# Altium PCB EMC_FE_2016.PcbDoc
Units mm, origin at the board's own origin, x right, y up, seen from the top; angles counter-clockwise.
Board outline 100 x 50 mm, 2 copper layers (Top Layer, Bottom Layer), stack 1.55 mm thick; 86 components, 30 nets, 176 pads, 0 vias.
Unrouted connection lines stored in the file: 116.
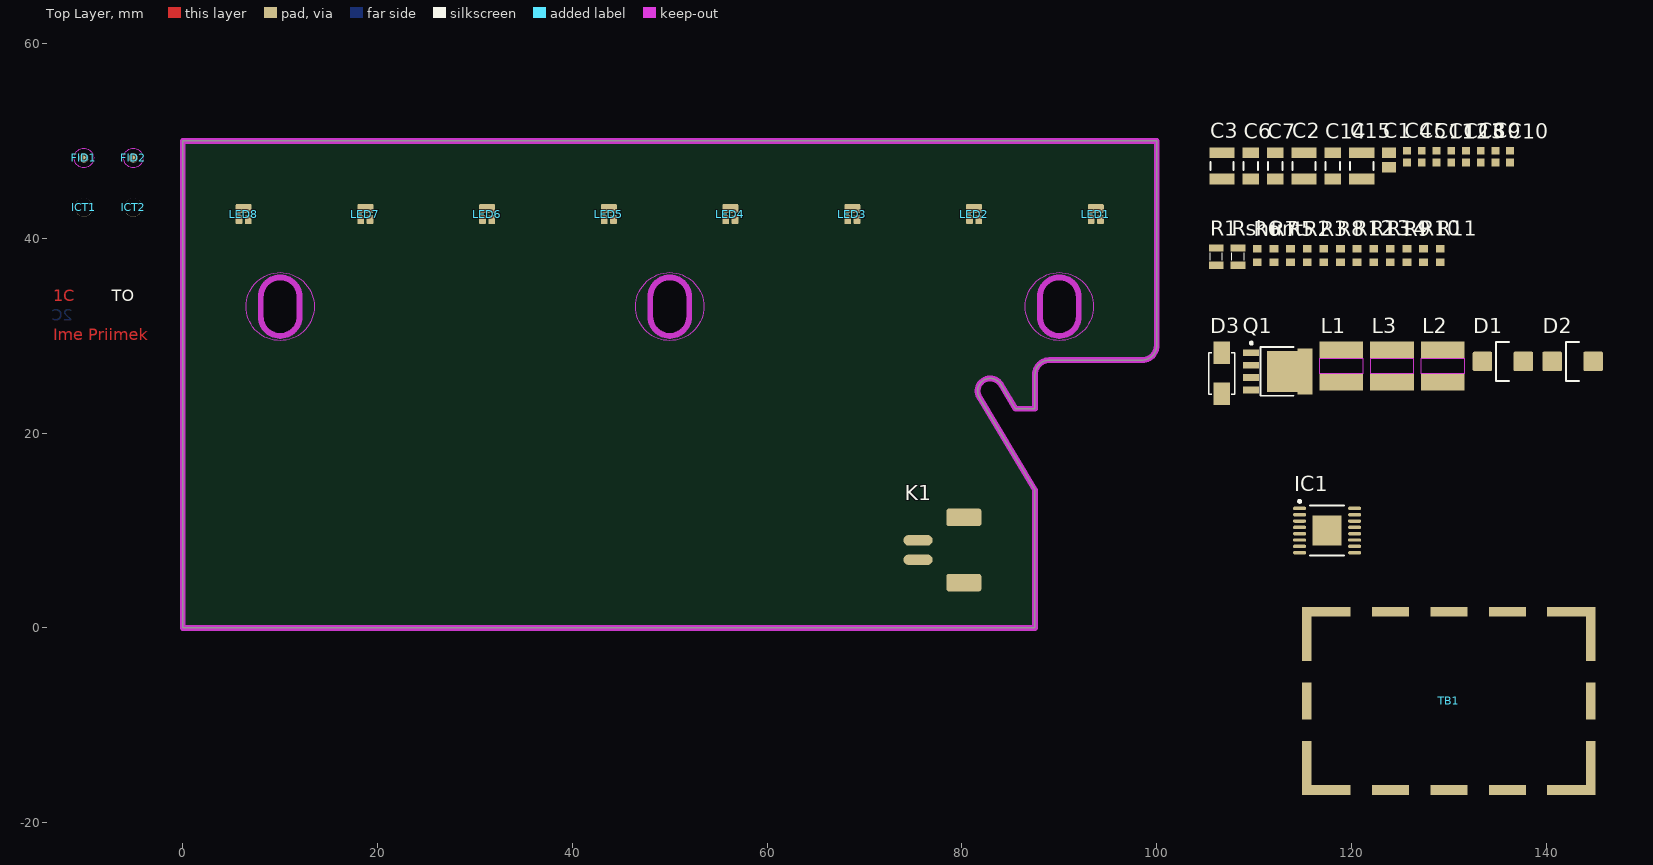
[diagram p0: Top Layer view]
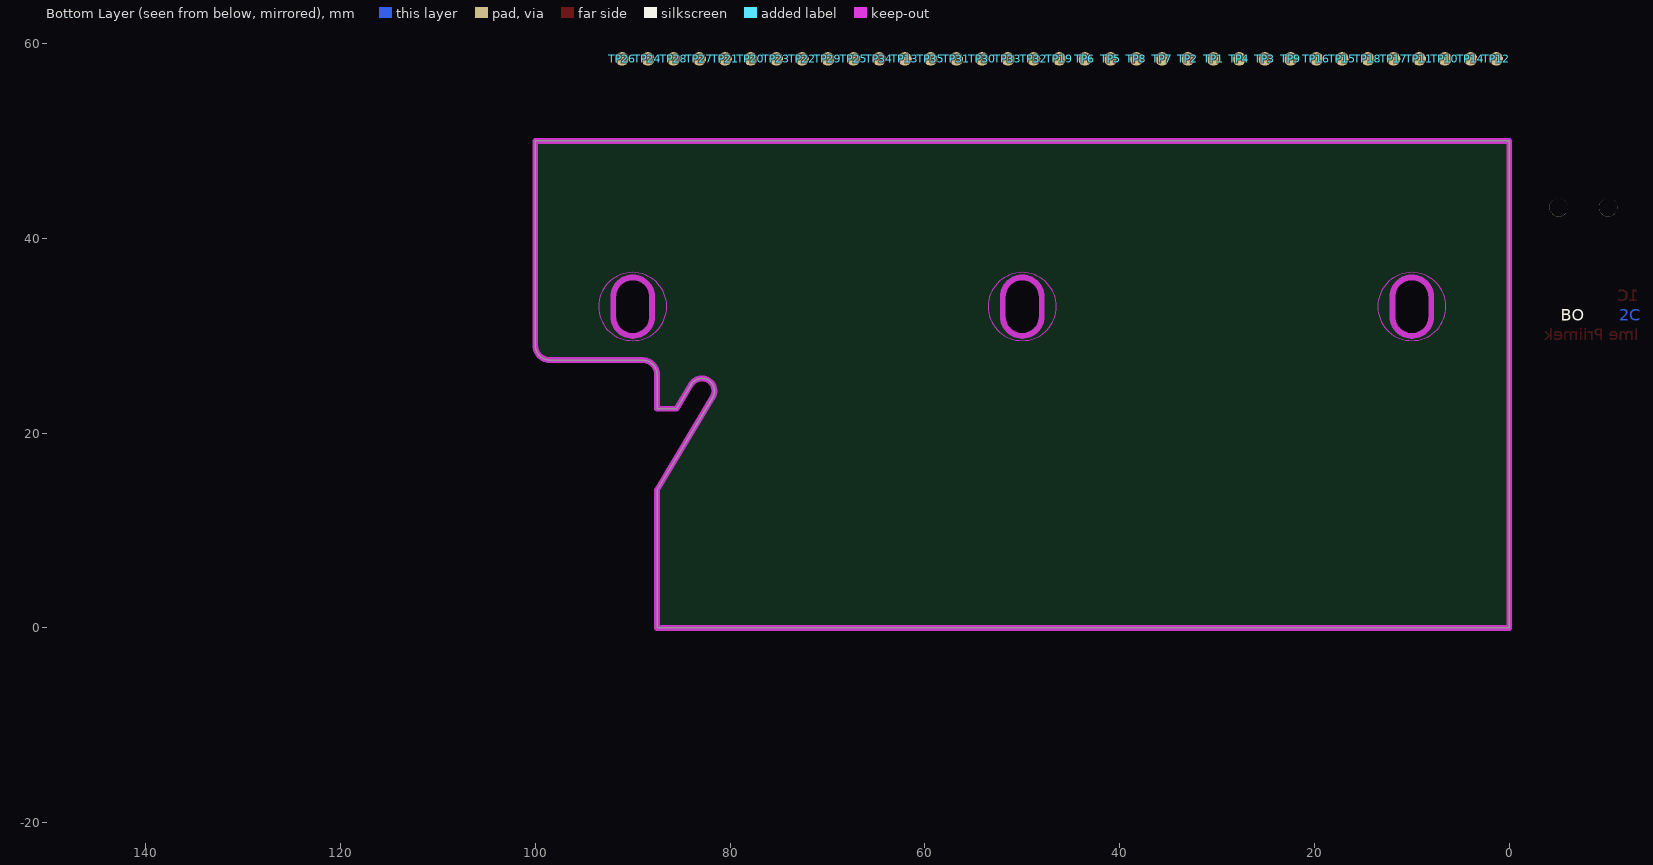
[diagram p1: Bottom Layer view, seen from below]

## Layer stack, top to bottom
Top Solder: solder mask 0.0102, Solder Resist, Dk 3.5
Top Layer: signal copper 0.07
Dielectric1: core 1.41, FR-4, Dk 4.8
Bottom Layer: signal copper 0.07
Bottom Solder: solder mask 0.0102, Solder Resist, Dk 3.5

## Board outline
0,0 0,50 100,50 100,29 cw(c98.5,29) 98.5,27.5 89,27.5 ccw(c89,26) 87.5,26 87.5,22.5 85.5,22.5 84,25 ccw(c82.897,24.338) 81.794,23.676 87.5,14.167 87.5,0
cut-out: 8,31.99 ccw(c10,31.99) 12,31.99 12,33.99 ccw(c10,33.99) 8,33.99
cut-out: 48,31.99 ccw(c50,31.99) 52,31.99 52,33.99 ccw(c50,33.99) 48,33.99
cut-out: 88,31.99 ccw(c90,31.99) 92,31.99 92,33.99 ccw(c90,33.99) 88,33.99

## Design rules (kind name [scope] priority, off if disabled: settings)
AssemblyTestPointUsage SilkToBoardRegionClearance [All] p2:
AssemblyTestPointUsage UnpouredPolygon [All] p3:
AssemblyTestpoint [(IsPad And OnBottomLayer)] p1: testpointundercomponent=TRUE minsize=1.016 maxsize=2.54 preferedsize=1.524 minholesize=0 maxholesize=1.016 preferedholesize=0.813 testpointgrid=0.025 usegrid=FALSE gridtolerance=0 allowsidebottom=TRUE
Clearance Clearance_GND [(InNamedPolygon('Bottom Layer-No Net'))] p1: gap=0.3
Clearance Clearance_LED [HasFootprint('LUXEON_F_CW')] p2: gap=0.25
Clearance [All] p3: gap=0.3
FabricationTestpoint [(IsPad And OnBottomLayer)] p1: side=2 testpointundercomponent=FALSE minsize=1.016 maxsize=2.54 preferedsize=1.524 minholesize=0 maxholesize=1.016 preferedholesize=0.813 testpointgrid=0.025 allowsidebottom=TRUE usegrid=FALSE gridtolerance=0 minspacing=2.54 boardedgeclearance=1
Height [All] p1: minheight=-1 maxheight=50 prefheight=12.7
HoleSize [All] p1: absolutevalues=TRUE maxlimit=6.096 minlimit=0.356 maxpercent=80.000 minpercent=20.000
HoleToHoleClearance [All] p1: gap=0.203 allowstackedmicrovias=TRUE
MinimumSolderMaskSliver [All] p1: minsoldermaskwidth=0.076
PlaneClearance [All] p1: clearance=0.305
PlaneConnect [All] p1: planeconnectstyle=Relief reliefexpansion=0.508 reliefentries=4 reliefconductorwidth=0.3 reliefairgap=0.3
PolygonConnect PolygonConnect_via [IsVia] p1: connectstyle=Direct reliefconductorwidth=0.254 reliefentries=4 polygonreliefangle="90 Angle" airgapwidth=0.254
PolygonConnect PolygonConnect_PadGND [(HasFootprint('BMI-S-209-F') OR HasFootprint('MXA16A_M')) AND InNet('GND')] p2: connectstyle=Direct reliefconductorwidth=0.254 reliefentries=4 polygonreliefangle="90 Angle" airgapwidth=0.254
PolygonConnect [All] p3: connectstyle=Relief reliefconductorwidth=0.305 reliefentries=4 polygonreliefangle="90 Angle" airgapwidth=0.305
RoutingVias [All] p1: holewidth=0.5 width=0.9 viastyle="Through Hole" minholewidth=0.4 minwidth=0.7 maxholewidth=0.7 maxwidth=1.2
ShortCircuit fill [IsFill And IsKeepOut vs IsPad] p1: allowed=TRUE
ShortCircuit ShortCircuit_GND [InNet('AGND') OR InNet('GND') OR InNet('QGND') OR InNet('PGND') OR InNet('REF_GND') vs InNet('AGND') OR InNet('GND') OR InNet('QGND') OR InNet('PGND') OR InNet('REF_GND')] p2: allowed=TRUE
ShortCircuit [All] p3: allowed=FALSE
SilkToBoardRegionClearance SilkToBoardRegionClearance_1 [All] p1:
SilkToSilkClearance [All] p1: silktosilkclearance=0.102
SilkToSolderMaskClearance SilkscreenOverComponentPads [IsPad] p1: minsilkscreentomaskgap=0.05 clearancetoexposedcopper=TRUE
SolderMaskExpansion [All] p1: expansion=0.102
UnpouredPolygon UnpouredPolygon_1 [All] p1:
Width [All] p1: maxlimit=0.5 minlimit=0.2 preferedwidth=0.3
17 further rules are at their usual default settings.

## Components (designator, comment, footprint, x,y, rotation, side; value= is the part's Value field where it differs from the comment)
C1 "?" C0805 123.852,48.042 r90 top
C2 "?" C1210 115.128,47.442 r90 top
C3 "?" C1210 106.704,47.442 r90 top
C4 "?" C0603 125.712,48.39 r90 top
C5 "?" C0603 127.223,48.39 r90 top
C6 "?" C1206 109.662,47.442 r90 top
C7 "?" C1206 112.17,47.442 r90 top
C8 "?" C0603 133.268,48.39 r90 top
C9 "?" C0603 134.779,48.39 r90 top
C10 "?" C0603 136.29,48.39 r90 top
C11 "?" C0603 128.734,48.39 r90 top
C12 "?" C0603 130.245,48.39 r90 top
C13 "?" C0603 131.756,48.39 r90 top
C14 "?" C1206 118.086,47.442 r90 top
C15 "?" C1210 121.044,47.442 r90 top
D1 "SS26" DO-214AA 135.549,27.367 r0 top
D2 "SS26" DO-214AA 142.707,27.367 r0 top
D3 "Bidirectional, 400 W, 36 VDC" DO-214AC_Bidirectional 106.665,26.14 r90 top
FID1 "Fiducial" FIDUCIAL -10.16,48.26 r90 top
FID2 "Fiducial" FIDUCIAL -5.08,48.26 r90 top
IC1 "TPS92690-Q1" MXA16A_L 117.5,10 r0 top
ICT1 "ICT" ICT_19 -10.16,43.18 r90 top
ICT2 "ICT" ICT_19 -5.08,43.18 r90 top
K1 "BM02B-PASS" BM02B-PASS 79,8 r90 top
L1 "?" WE-PD2A_4532 118.941,26.89 r0 top
L2 "?" WE-PD2A_4532 129.364,26.89 r0 top
L3 "?" WE-PD2A_4532 124.152,26.89 r0 top
LED1 "LFXH-C1A-0100" LUXEON_F_CW 93.75,42.525 r0 top locked
LED2 "LFXH-C1A-0100" LUXEON_F_CW 81.25,42.525 r0 top locked
LED3 "LFXH-C1A-0100" LUXEON_F_CW 68.75,42.525 r0 top locked
LED4 "LFXH-C1A-0100" LUXEON_F_CW 56.225,42.525 r0 top locked
LED5 "LFXH-C1A-0100" LUXEON_F_CW 43.75,42.525 r0 top locked
LED6 "LFXH-C1A-0100" LUXEON_F_CW 31.25,42.525 r0 top locked
LED7 "LFXH-C1A-0100" LUXEON_F_CW 18.75,42.525 r0 top locked
LED8 "LFXH-C1A-0100" LUXEON_F_CW 6.25,42.525 r0 top locked
Q1 "BUK9Y59-60E" LFPAK56 112.436,26.342 r0 top
R1 "?" R0805 106.118,38.12 r90 top
R2 "?" R0603 115.448,38.242 r90 top
R3 "100" R0603 117.156,38.242 r90 top
R5 "?" R0603 113.74,38.242 r90 top
R6 "?" R0603 110.324,38.242 r90 top
R7 "?" R0603 112.032,38.242 r90 top
R8 "?" R0603 118.864,38.242 r90 top
R9 "?" R0603 125.696,38.242 r90 top
R10 "?" R0603 127.404,38.242 r90 top
R11 "?" R0603 129.112,38.242 r90 top
R12 "?" R0603 120.572,38.242 r90 top
R13 "?" R0603 122.28,38.242 r90 top
R14 "?" R0603 123.988,38.242 r90 top
Rshunt "?" R0805 108.353,38.12 r90 top
TB1 "BMI-S-209-F" BMI-S-209-F 130,-7.5 r180 top
TP1 "TP?" Test_point_14 30.36,58.426 r180 bottom
TP2 "TP?" Test_point_14 33,58.426 r180 bottom
TP3 "TP?" Test_point_14 25.08,58.426 r180 bottom
TP4 "TP?" Test_point_14 27.72,58.426 r180 bottom
TP5 "TP?" Test_point_14 40.92,58.426 r180 bottom
TP6 "TP?" Test_point_14 43.56,58.426 r180 bottom
TP7 "TP?" Test_point_14 35.64,58.426 r180 bottom
TP8 "TP?" Test_point_14 38.28,58.426 r180 bottom
TP9 "TP?" Test_point_14 22.44,58.426 r180 bottom
TP10 "TP?" Test_point_14 6.6,58.426 r90 bottom
TP11 "TP?" Test_point_14 9.24,58.426 r90 bottom
TP12 "TP?" Test_point_14 1.32,58.426 r90 bottom
TP13 "TP?" Test_point_14 62.04,58.426 r90 bottom
TP14 "TP?" Test_point_14 3.96,58.426 r90 bottom
TP15 "TP?" Test_point_14 17.16,58.426 r90 bottom
TP16 "TP?" Test_point_14 19.8,58.426 r90 bottom
TP17 "TP?" Test_point_14 11.88,58.426 r90 bottom
TP18 "TP?" Test_point_14 14.52,58.426 r90 bottom
TP19 "TP?" Test_point_14 46.2,58.426 r90 bottom
TP20 "TP?" Test_point_14 77.88,58.426 r90 bottom
TP21 "TP?" Test_point_14 80.52,58.426 r90 bottom
TP22 "TP?" Test_point_14 72.6,58.426 r90 bottom
TP23 "TP?" Test_point_14 75.24,58.426 r90 bottom
TP24 "TP?" Test_point_14 88.44,58.426 r90 bottom
TP25 "TP?" Test_point_14 67.32,58.426 r90 bottom
TP26 "TP?" Test_point_14 91.08,58.426 r90 bottom
TP27 "TP?" Test_point_14 83.16,58.426 r90 bottom
TP28 "TP?" Test_point_14 85.8,58.426 r90 bottom
TP29 "TP?" Test_point_14 69.96,58.426 r90 bottom
TP30 "TP?" Test_point_14 54.12,58.426 r90 bottom
TP31 "TP?" Test_point_14 56.76,58.426 r90 bottom
TP32 "TP?" Test_point_14 48.84,58.426 r90 bottom
TP33 "TP?" Test_point_14 51.48,58.426 r90 bottom
TP34 "TP?" Test_point_14 64.68,58.426 r90 bottom
TP35 "TP?" Test_point_14 59.4,58.426 r90 bottom

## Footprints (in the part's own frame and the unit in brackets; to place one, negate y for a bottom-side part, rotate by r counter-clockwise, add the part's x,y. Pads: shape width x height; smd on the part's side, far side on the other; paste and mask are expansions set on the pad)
BM02B-PASS [mm]
  oval 1.1x3 smd: 1(1,3.5) 2(-1,3.5)
  rrect30% 1.8x3.6 smd: M1(3.35,-1.2) M2(-3.35,-1.2)
  body extent -4,-2.85 4,4.25, height 9
BMI-S-209-F [mm]
  rect 1x5.55 smd: 1(-14.58,6.875) 3(-14.58,-6.875) 7(14.58,-6.875) 9(14.58,6.875)
  rect 4.98x1 smd: 1(-12.59,9.15) 3(-12.59,-9.15) 7(12.59,-9.15) 9(12.59,9.15)
  rect 1x3.8 smd: 2(-14.58,0) 8(14.58,0)
  rect 3.8x1 smd: 4(-6,-9.15) 5(0,-9.15) 6(6,-9.15) 10(6,9.15) 11(0,9.15) 12(-6,9.15)
  body extent -14.98,-9.55 14.98,9.55, height 22
C0603 [mm]
  rect 0.8x0.8 smd: 1(-0.6,0) 2(0.6,0)
  body extent -0.8,-0.4 0.8,0.4, height 0.8
C0805 [mm] "Chip Capacitor, Body 2.0x1.3mm, IPC High Density"
  rect 1.1x1.4 smd: 1(-0.75,0) 2(0.75,0)
  body extent -1.1,-0.72 1.1,0.72, height 1.4
C1206 [mm] "Chip Capacitor, Body 3.2x1.6mm, IPC High Density"
  rect 1.1x1.7 smd: 1(-1.35,0) 2(1.35,0)
  silkscreen extent -0.4,-0.75 0.4,0.75, body extent -1.7,-0.9 1.7,0.9, height 1.3
C1210 [mm] "Chip Capacitor, Body 3.2x2.5mm, IPC High Density"
  rect 1.1x2.6 smd: 1(-1.35,0) 2(1.35,0)
  silkscreen extent -0.4,-1.2 0.4,1.2, body extent -1.7,-1.35 1.7,1.35, height 1.3
DO-214AA [mm]
  rrect15% 2x2 smd: A(2.1,0) K(-2.1,0)
  silkscreen extent -0.7,-2 0.63,2, body extent -2.75,-1.95 2.75,1.95, height 2.45
DO-214AC_Bidirectional [mm] "WE-TVSP Power TVS Diode, DO-214AC, Bidirectional"
  rect 2.3x1.7 smd: 1(-2.1,0) 2(2.1,0)
  silkscreen extent -2.12,-1.34 2.12,1.34, body extent -2.56,-1.33 2.56,1.34, height 2.25
FIDUCIAL [mm]
  round 1 smd paste-2 mask+0.5: F(0,0)
  Top Layer keep-out region: 0,-1 -0.383,-0.924 -0.707,-0.707 -0.924,-0.383 -1,0 -1,0 -0.924,0.383 -0.707,0.707 -0.383,0.924 0,1 0,1 0.383,0.924 0.707,0.707 0.924,0.383 1,0 1,0 0.924,-0.383 0.707,-0.707 0.383,-0.924 0,-1
ICT_19 [mm]
  round 1.9 hole 1.9 unplated paste-2: 0(0,0)
LFPAK56 [mm] "SOT-669, 5-Pads, Body 5,15x5,86mm (max), IPC High Density"
  rect 4.6x4.2 smd paste-10: D(1.2,0)
  rect 1.5x4.7 smd paste-10: D(2.794,0)
  rect 1.6x0.7 smd: G(-2.75,-1.905) S(-2.75,-0.635) S(-2.75,0.635) S(-2.75,1.905)
  silkscreen extent -2.85,-2.5 1.6,3.02, body extent -3.42,-2.5 3.35,2.5, height 1.2
LUXEON_F_CW [mm]
  rrect30% 0.7x0.9 smd mask+0.051: A(0.475,-0.6) K(-0.475,-0.6)
  rrect30% 1.65x0.9 smd mask+0.051: T(0,0.55)
  body extent -0.95,-1.18 0.95,1.13, height 0.73
MXA16A_L [mm]
  oval 1.35x0.35 smd: 1(-2.825,2.275) 2(-2.825,1.625) 3(-2.825,0.975) 4(-2.825,0.325) 5(-2.825,-0.325) 6(-2.825,-0.975) 7(-2.825,-1.625) 8(-2.825,-2.275) 9(2.825,-2.275) 10(2.825,-1.625) 11(2.825,-0.975) 12(2.825,-0.325) 13(2.825,0.325) 14(2.825,0.975) 15(2.825,1.625) 16(2.825,2.275)
  rect 3x3.1 smd: 17(0,0)
  silkscreen extent -2.95,-2.55 1.75,3.12, body extent -3.2,-2.5 3.2,2.5, height 1
R0603 [mm]
  rect 0.8x0.9 smd: 1(-0.7,0) 2(0.7,0)
  body extent -0.8,-0.41 0.8,0.41, height 0.45
R0805 [mil]
  rect 30x60 smd: 1(-35,0) 2(35,0)
  silkscreen extent -15,-25 15,25, body extent -39,-25 39,24, height 31
Test_point_14 [mm]
  round 1.4 smd paste-1: T(0,0)
WE-PD2A_4532 [mm] "WE-PD2A SMD Power Inductor, 4532"
  rect 4.5x1.75 smd: 1(0,1.625) 2(0,-1.625)
  Top Layer keep-out region: -2.25,-0.75 2.25,-0.75 2.25,0.75 -2.25,0.75
  body extent -2.16,-2 2.16,2, height 3.2

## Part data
C1 C2 C3 C4 C5 C6 C7 C8 C9 C10 C11 C12 C13 C14 C15: library part C, "Capacitor"
D1 D2: "Schottky Diode 2A"
D3: library part "WE-TVSP DO-214AC, 824501361", "WE-TVSP Power TVS Diode, bidirectional, 400 W, 36 VDC"
FID1 FID2: "according to IPC-7351 - is a 1mm diameter round dot with 2mm solder mask opening"
IC1: "N-Channel Controller for Dimmable LED Drives With Low-Side Current Sense"
ICT1 ICT2: "Alignmnt holes for In Circuit Testing"
K1: "Wire-To-Board Connector, PA Series, Surface Mount, Header, 2, 2 mm, Tin Plated Contacts"
L1 L2 L3: library part "WE-PD2A 4532, 7847730", "WE-PD2A SMD Power Inductor, Inductance = 1.0 μH"
LED1 LED2 LED3 LED4 LED5 LED6 LED7 LED8: "high-power, 1.9mm x 2.3mm LED, Cool White"
Q1: "N-MOS, 16.7A, 60V, 0.044 ohm, 10V, 1.7V"
R1 R2 R3 R5 R6 R7 R8 R9 R10 R11 R12 R13 R14: library part R, "Resistor"
Rshunt: library part R_shunt, "Resistor"
TB1: "SURFACE MOUNT,  EMI SHIELD"
TP1 TP2 TP3 TP4 TP5 TP6 TP7 TP8 TP9 TP10 TP11 TP12 TP13 TP14 TP15 TP16 TP17 TP18 TP19 TP20 TP21 TP22 TP23 TP24 TP25 TP26 TP27 TP28 TP29 TP30 TP31 TP32 TP33 TP34 TP35: library part Test_point, "In-circuit test probe contact"

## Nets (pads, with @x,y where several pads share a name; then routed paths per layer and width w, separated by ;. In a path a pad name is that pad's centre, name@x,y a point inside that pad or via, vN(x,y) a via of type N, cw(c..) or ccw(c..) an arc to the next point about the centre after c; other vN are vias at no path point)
CSP: C8.1 IC1.11 R5.2 TP30.T
GND: C1.1 C2.1 C3.1 C4.1 C5.1 C6.1 C7.1 C8.2 C9.1 C10.2 C11.1 C12.1 C13.1 C14.2 C15.1 D3.2 IC1.7 IC1.12 IC1.17 K1.2 K1.M1 K1.M2 Q1.S R1.1 R6.1 R9.2 R10.2 R11.2 R13.1 Rshunt.1 TB1.1 TB1.2 TB1.3 TB1.4 TB1.5 TB1.6 TB1.7 TB1.8 TB1.9 TB1.10 TB1.11 TB1.12 TP11.T TP21.T TP28.T TP35.T
IADJ: C9.2 IC1.10 R6.2 R7.2 TP32.T
ILIM: C11.2 IC1.8 R8.1 R9.1 TP34.T
IS: C5.2 IC1.14 R3.2 TP23.T
LED+: C7.2 L3.2 LED1.A TP15.T
LED-: LED8.K R5.1 Rshunt.2 TP31.T
NetC2_2: C2.2 D1.K L1.1 TP2.T
NetC4_2: C4.2 Q1.G R2.1 TP24.T
NetC6_2: C6.2 D2.K L3.1 TP14.T
NetC12_2: C12.2 IC1.6 TP29.T
NetC13_2: C13.2 IC1.5 TP27.T
NetC14_1: C14.1 IC1.15 TP20.T
NetD2_A: D2.A L2.2 Q1.D R3.1 TP13.T
NetIC1_1: IC1.1 R12.1 TP17.T
NetIC1_3: IC1.3 R11.1 TP22.T
NetIC1_4: IC1.4 R10.1 TP25.T
NetIC1_13: IC1.13 R2.2 TP26.T
NetLED1_K: LED1.K LED2.A TP4.T
NetLED2_K: LED2.K LED3.A TP5.T
NetLED3_K: LED3.K LED4.A TP6.T
NetLED4_K: LED4.K LED5.A TP7.T
NetLED5_K: LED5.K LED6.A TP8.T
NetLED6_K: LED6.K LED7.A TP9.T
NetLED7_K: LED7.K LED8.A TP10.T
NetR12_2: R12.2 R13.2 R14.2 TP16.T
OVP: IC1.2 TP19.T
SUPPLY: C3.2 C15.2 IC1.16 L1.2 L2.1 R14.1 TP3.T TP12.T TP18.T
UB: C1.2 D1.A D3.1 K1.1 R1.2 TP1.T
VREF: C10.1 IC1.9 R7.1 R8.2 TP33.T
pads on no net: FID1.F FID2.F ICT1.0 ICT2.0 LED1.T LED2.T LED3.T LED4.T LED5.T LED6.T LED7.T LED8.T

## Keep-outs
Keep-Out Layer:
  lines w0.6: 0,0 0,50 100,50 100,29 cw(c98.5,29) 98.5,27.5 89,27.5 ccw(c89,26) 87.5,26 87.5,22.5 85.5,22.5 84,25 ccw(c82.897,24.338) 81.794,23.676 87.5,14.167 87.5,0 0,0 ; 8,31.99 ccw(c10,31.99) 12,31.99 12,33.99 ccw(c10,33.99) 8,33.99 8,31.99 ; 48,31.99 ccw(c50,31.99) 52,31.99 52,33.99 ccw(c50,33.99) 48,33.99 48,31.99 ; 88,31.99 ccw(c90,31.99) 92,31.99 92,33.99 ccw(c90,33.99) 88,33.99 88,31.99
Multi-Layer:
  region: 90,29.5 cw(c90,33) 86.5,33 cw(c90,33) 90,36.5 cw(c90,33) 93.5,33 cw(c90,33)
  region: 50,29.5 cw(c50,33) 46.5,33 cw(c50,33) 50,36.5 cw(c50,33) 53.5,33 cw(c50,33)
  region: 10,29.5 cw(c10,33) 6.5,33 cw(c10,33) 10,36.5 cw(c10,33) 13.5,33 cw(c10,33)

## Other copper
Top Layer:
  text "1C" at -13.28,33.56 h1.2
  text "Ime Priimek" at -13.28,29.56 h1.2
Bottom Layer:
  text "2C" at -11.28,31.56 h1.2

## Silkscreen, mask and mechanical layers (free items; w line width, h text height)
Top Overlay:
  text "TO" at -7.28,33.56 h1.2
Bottom Overlay:
  text "BO" at -5.28,31.56 h1.2
Top Paste:
  text "TP" at -4.28,33.56 h1.2
Top Solder:
  region: 10,29.7 cw(c10,33) 6.7,33 cw(c10,33) 10,36.3 cw(c10,33) 13.3,33 cw(c10,33)
  region: 50,29.7 cw(c50,33) 46.7,33 cw(c50,33) 50,36.3 cw(c50,33) 53.3,33 cw(c50,33)
  region: 90,29.7 cw(c90,33) 86.7,33 cw(c90,33) 90,36.3 cw(c90,33) 93.3,33 cw(c90,33)
  text "TS" at -10.28,33.56 h1.2
Bottom Solder:
  region: 90,29.7 ccw(c90,33) 93.3,33 ccw(c90,33) 90,36.3 ccw(c90,33) 86.7,33 ccw(c90,33)
  region: 50,29.7 ccw(c50,33) 53.3,33 ccw(c50,33) 50,36.3 ccw(c50,33) 46.7,33 ccw(c50,33)
  region: 10,29.7 ccw(c10,33) 13.3,33 ccw(c10,33) 10,36.3 ccw(c10,33) 6.7,33 ccw(c10,33)
  text "BS" at -8.28,31.56 h1.2
Mechanical 1:
  circle w0.1: c90,33 r3.5
  circle w0.1: c50,33 r3.5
